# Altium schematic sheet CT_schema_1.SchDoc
size 501 x 485 mm
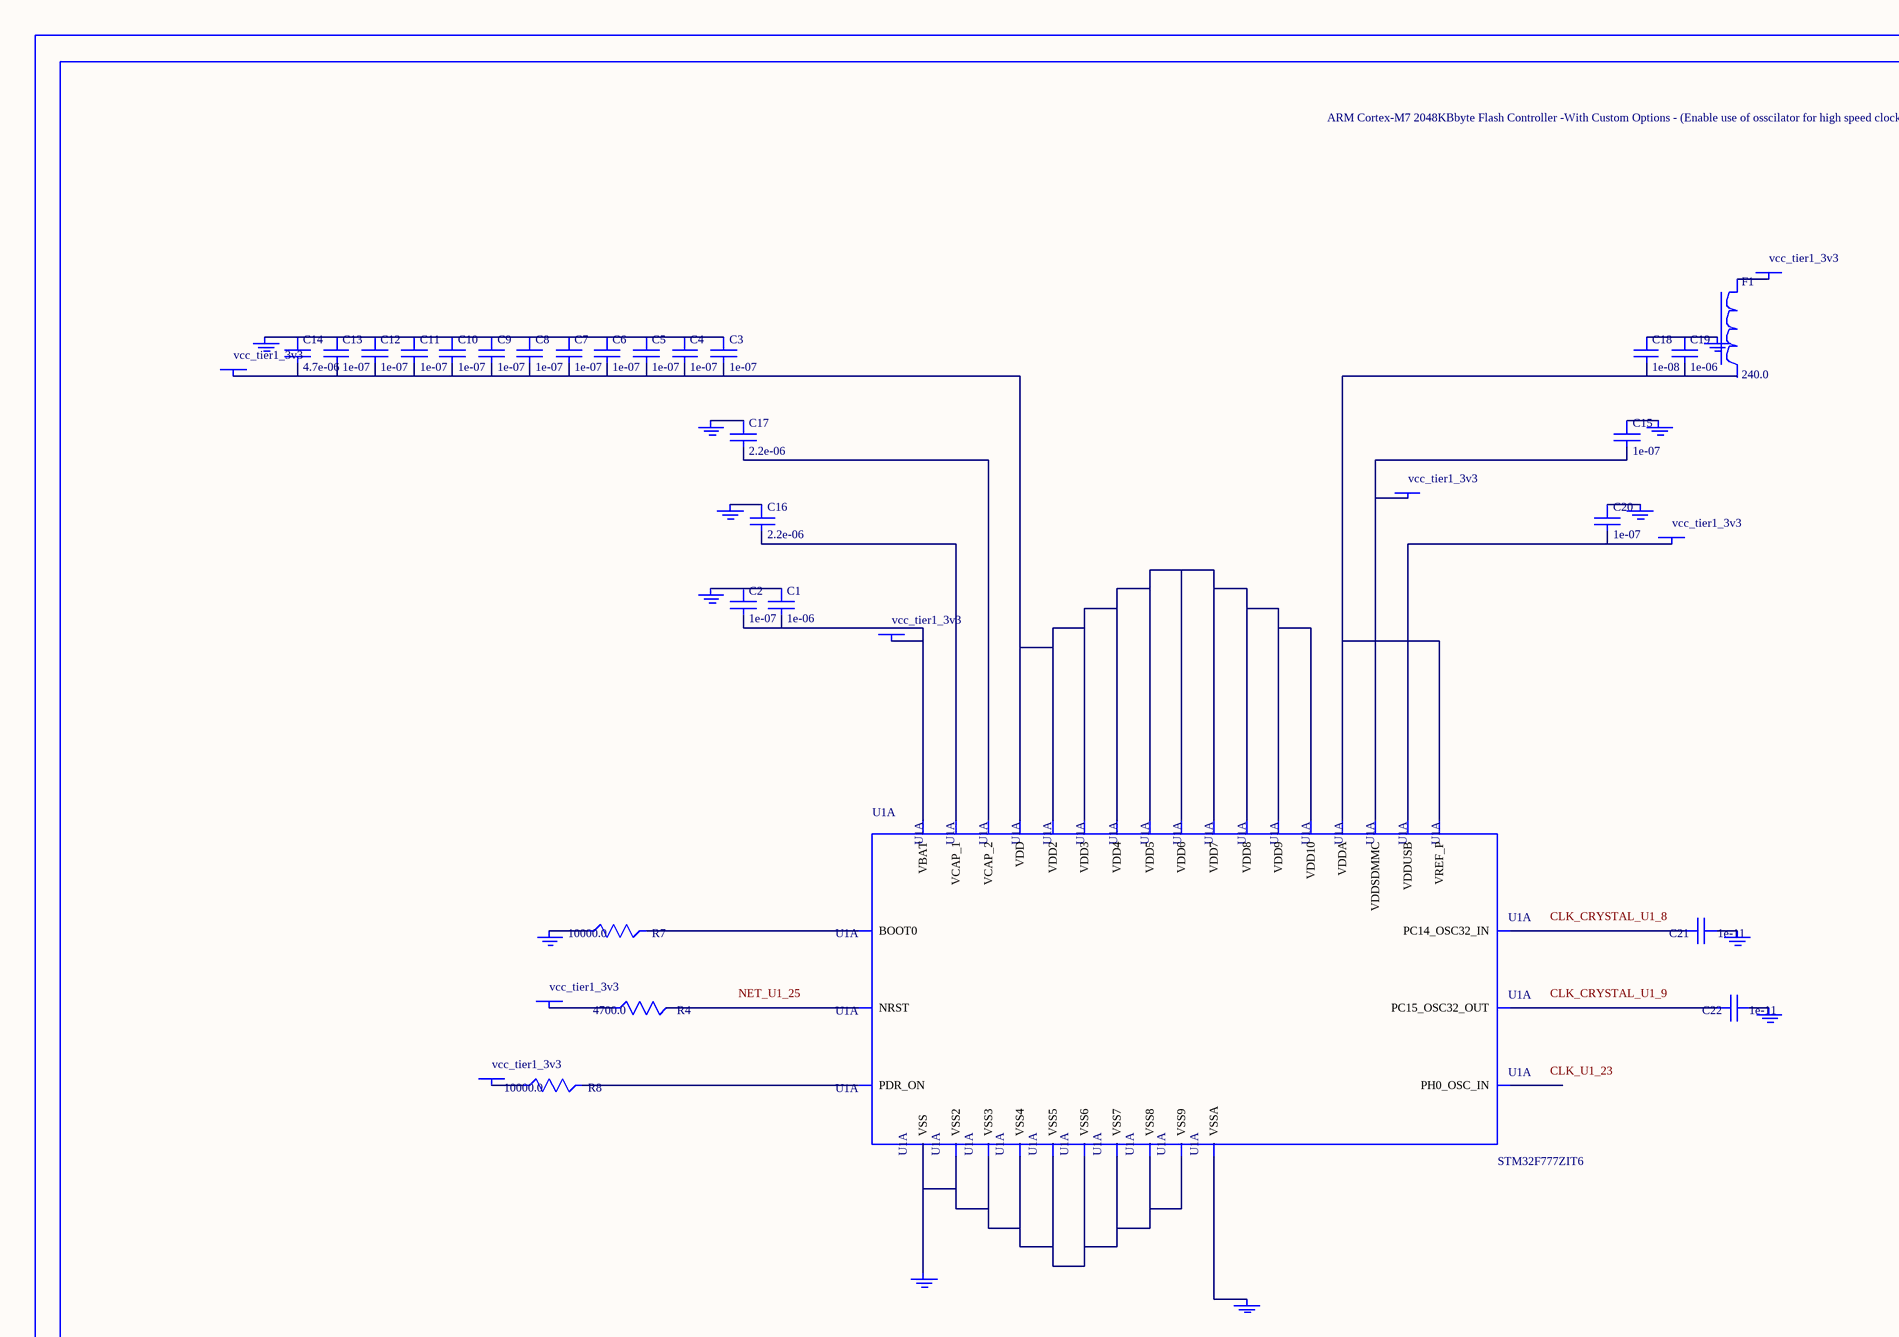
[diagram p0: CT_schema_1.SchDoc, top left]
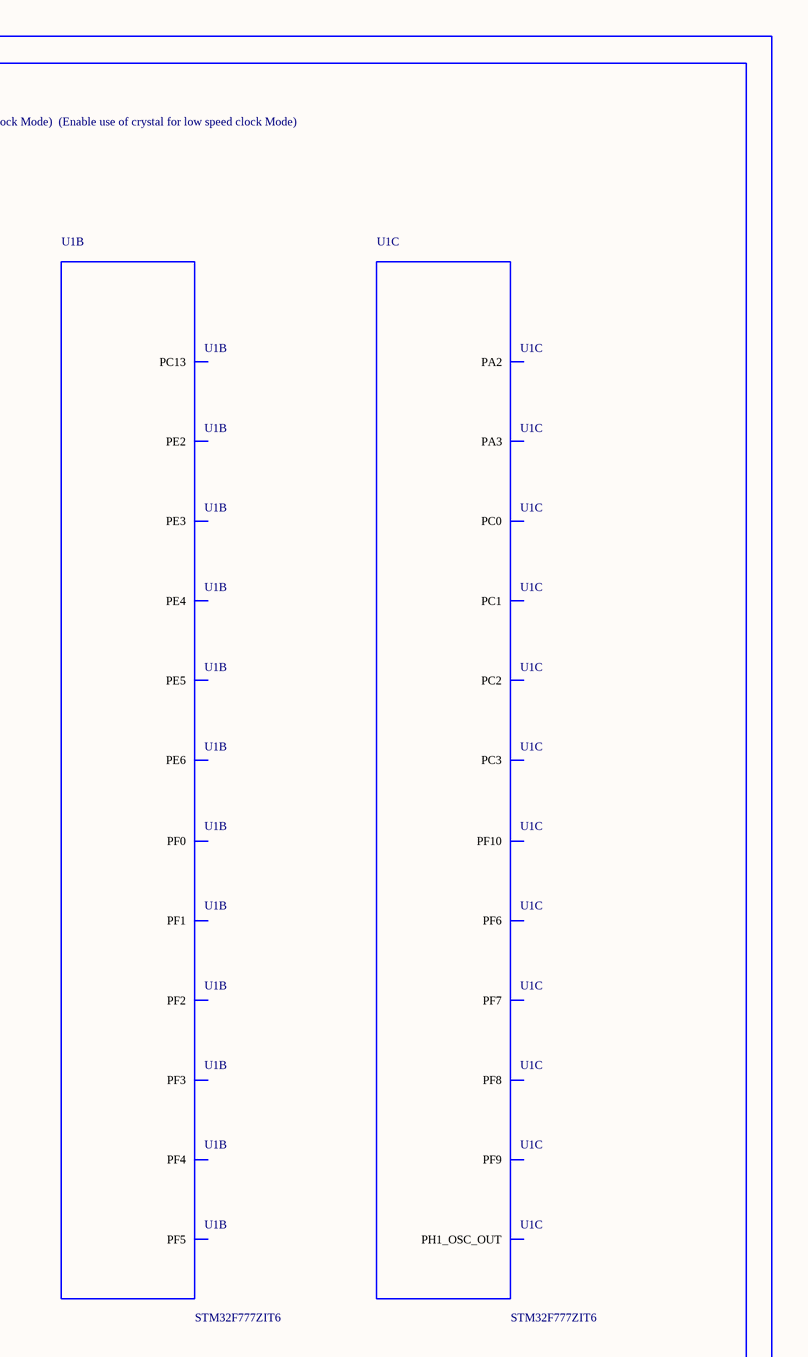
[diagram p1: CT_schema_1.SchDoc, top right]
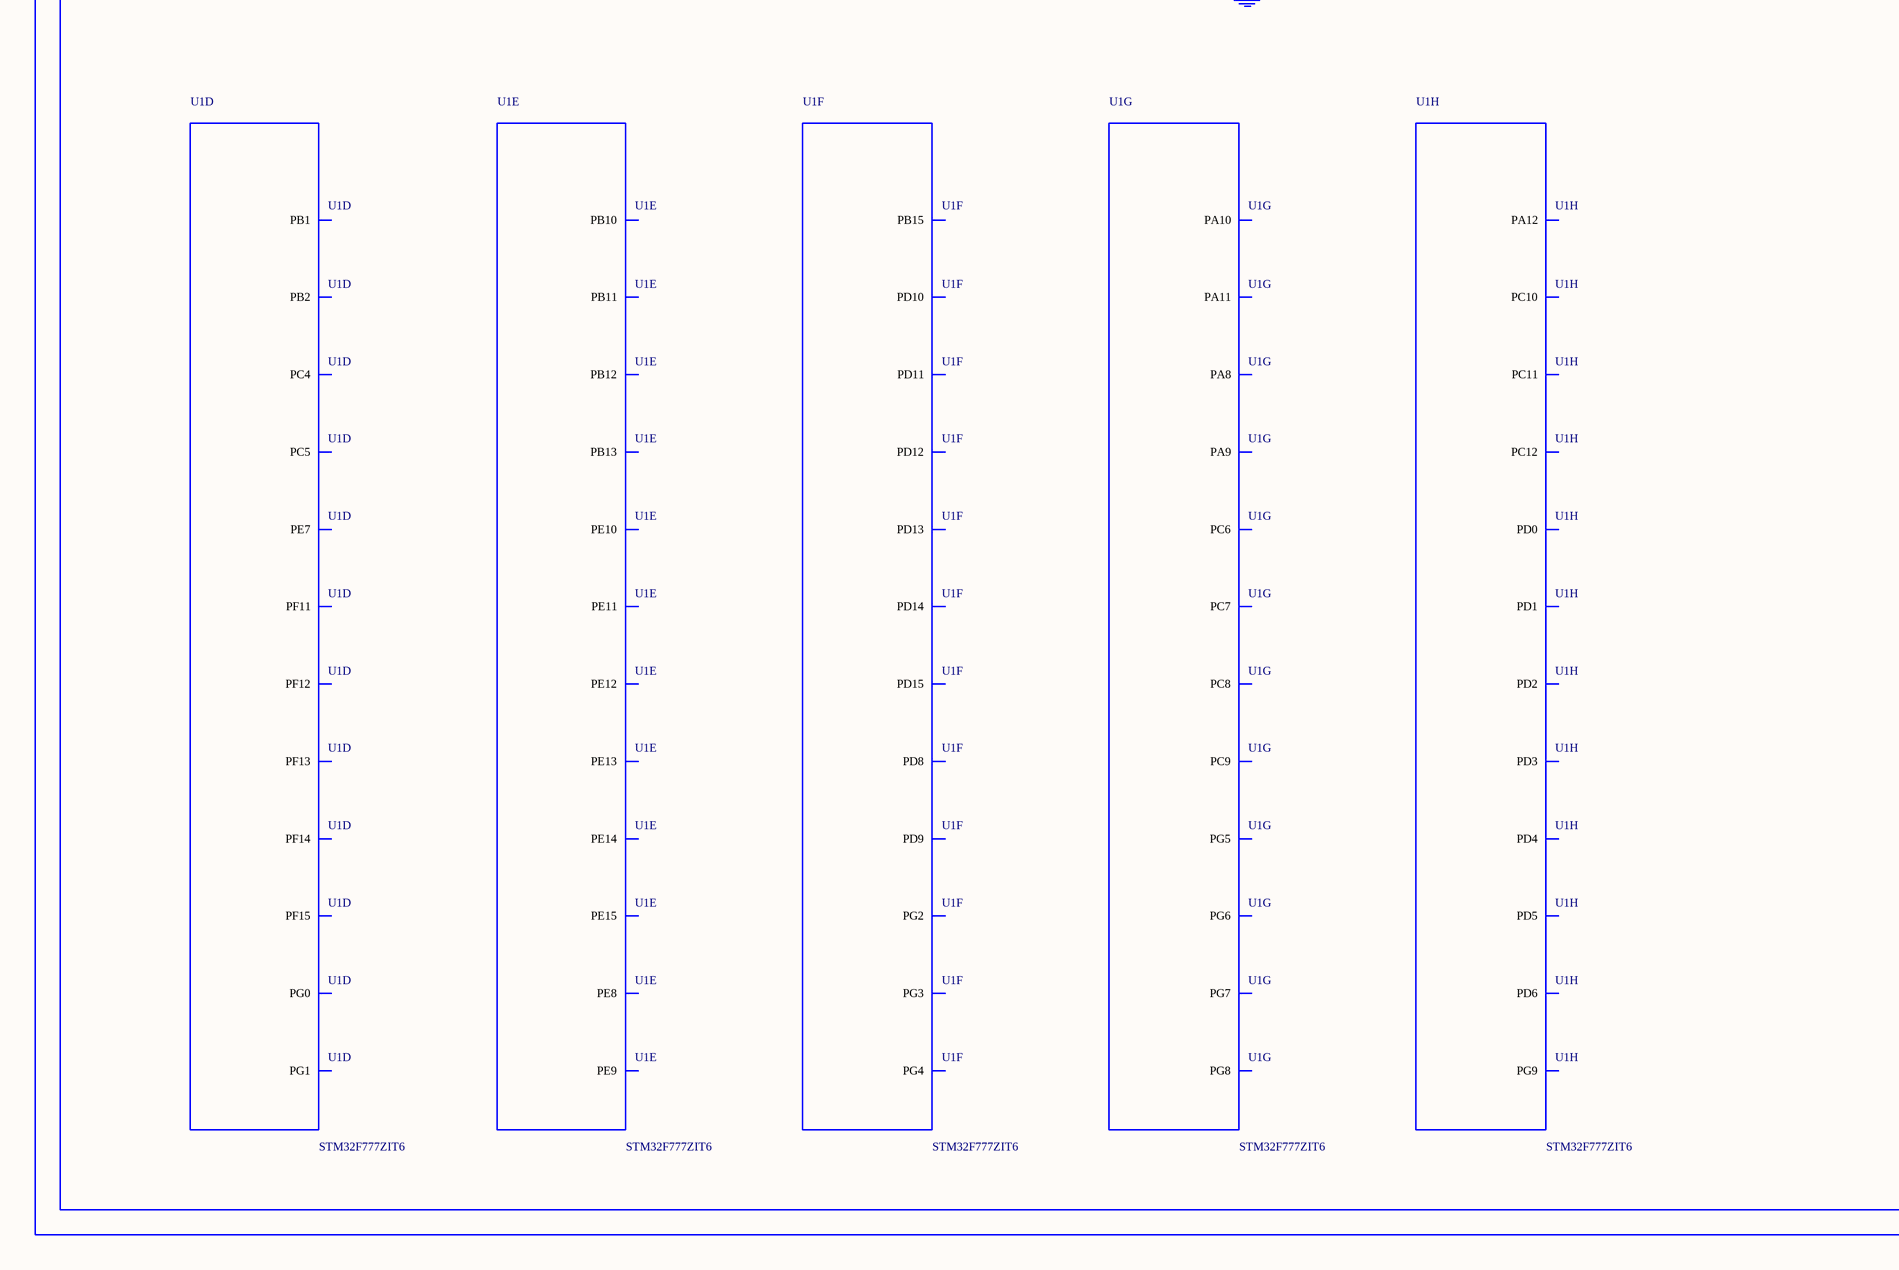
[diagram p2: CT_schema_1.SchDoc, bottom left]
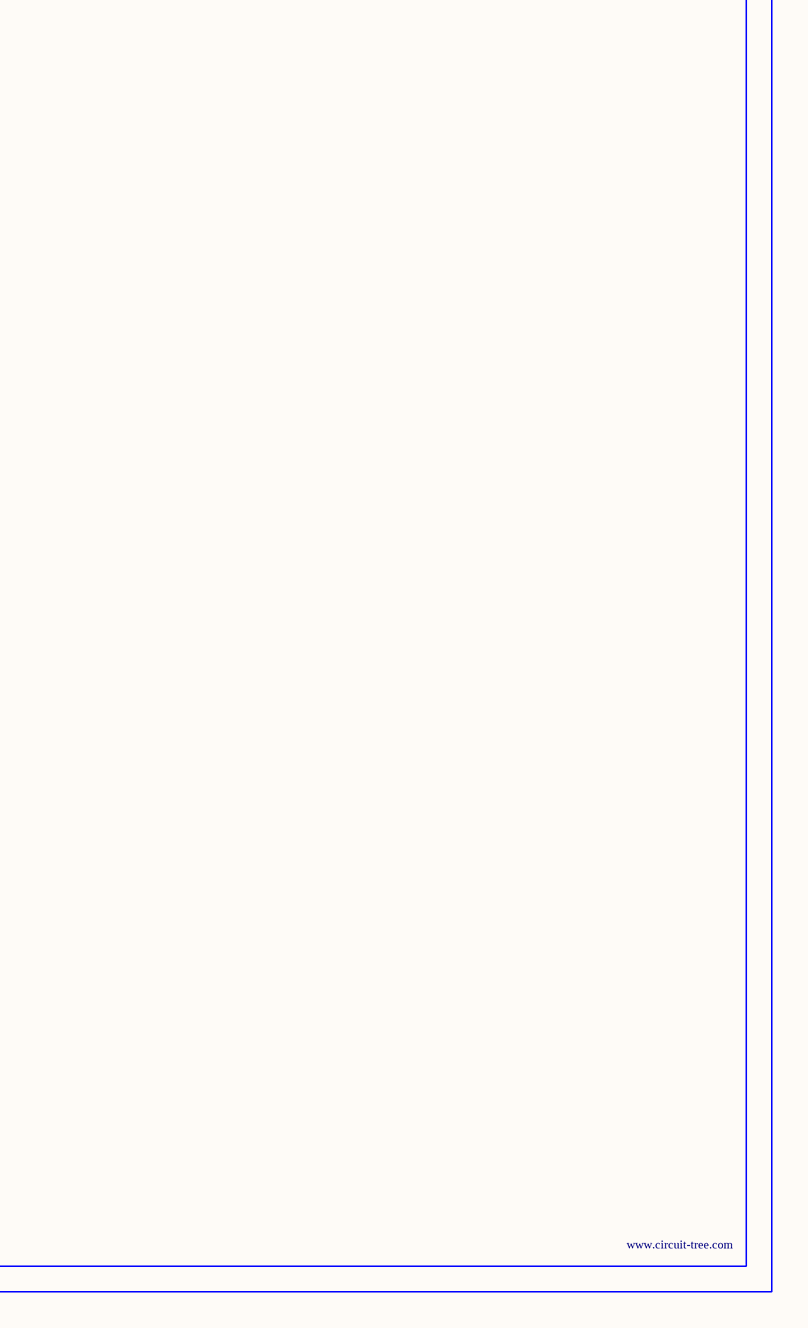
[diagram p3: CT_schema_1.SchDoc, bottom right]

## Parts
BORDER0  (no value)
C1  1e-06  [C0603]
C2  1e-07  [C0603]
C3  1e-07  [C0603]
C4  1e-07  [C0603]
C5  1e-07  [C0603]
C6  1e-07  [C0603]
C7  1e-07  [C0603]
C8  1e-07  [C0603]
C9  1e-07  [C0603]
C10  1e-07  [C0603]
C11  1e-07  [C0603]
C12  1e-07  [C0603]
C13  1e-07  [C0603]
C14  4.7e-06  [C0603]
C15  1e-07  [C0603]
C16  2.2e-06  [C0603]
C17  2.2e-06  [C0603]
C18  1e-08  [C0603]
C19  1e-06  [C0603]
C20  1e-07  [C0603]
C21  1e-11  [C0402]
C22  1e-11  [C0402]
F1  240.0  [L0603]
GND_INSTANCE_0_0  (no value)
GND_INSTANCE_0_1  (no value)
GND_INSTANCE_0_2  (no value)
GND_INSTANCE_0_3  (no value)
GND_INSTANCE_0_4  (no value)
GND_INSTANCE_0_5  (no value)
GND_INSTANCE_0_6  (no value)
GND_INSTANCE_0_7  (no value)
GND_INSTANCE_0_8  (no value)
GND_INSTANCE_0_9  (no value)
GND_INSTANCE_0_10  (no value)
GND_INSTANCE_0_11  (no value)
POWER_INSTANCE_0_0  vcc_tier1_3v3
POWER_INSTANCE_0_1  vcc_tier1_3v3
POWER_INSTANCE_0_2  vcc_tier1_3v3
POWER_INSTANCE_0_3  vcc_tier1_3v3
POWER_INSTANCE_0_4  vcc_tier1_3v3
POWER_INSTANCE_0_5  vcc_tier1_3v3
POWER_INSTANCE_0_6  vcc_tier1_3v3
R4  4700.0  [R0603]
R7  10000.0  [R0603]
R8  10000.0  [R0603]
U1  STM32F777ZIT6  [LQFP144]  (parts A,B,C,D,E,F,G,H of 13)

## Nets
NetC1_1: C1.1 C2.1 GND_INSTANCE_0_0.0(GND)
NetC1_2: C1.2 C2.2 POWER_INSTANCE_0_0.0(PWR) U1.6(VBAT)
NetC3_1: C3.1 C4.1 C5.1 C6.1 C7.1 C8.1 C9.1 C10.1 C11.1 C12.1 C13.1 C14.1 GND_INSTANCE_0_3.0(GND)
NetC3_2: C3.2 C4.2 C5.2 C6.2 C7.2 C8.2 C9.2 C10.2 C11.2 C12.2 C13.2 C14.2 POWER_INSTANCE_0_1.0(PWR) U1.17(VDD) U1.30(VDD2) U1.39(VDD3) U1.52(VDD4) U1.62(VDD5) U1.72(VDD6) U1.84(VDD7) U1.108(VDD8) U1.131(VDD9) U1.144(VDD10)
NetC15_1: C15.1 GND_INSTANCE_0_9.0(GND)
NetC15_2: C15.2 POWER_INSTANCE_0_4.0(PWR) U1.121(VDDSDMMC)
NetC16_1: C16.1 GND_INSTANCE_0_6.0(GND)
NetC16_2: C16.2 U1.71(VCAP_1)
NetC17_1: C17.1 GND_INSTANCE_0_8.0(GND)
NetC17_2: C17.2 U1.106(VCAP_2)
NetC18_1: C18.1 C19.1 GND_INSTANCE_0_5.0(GND)
NetC18_2: C18.2 C19.2 U1.32(VREF_P) U1.33(VDDA)
NetC20_1: C20.1 GND_INSTANCE_0_7.0(GND)
NetC20_2: C20.2 POWER_INSTANCE_0_3.0(PWR) U1.95(VDDUSB)
NetC21_1: C21.1 GND_INSTANCE_0_1.0(GND)
NetC21_2: C21.2 U1.8(PC14_OSC32_IN)
NetC22_1: C22.1 GND_INSTANCE_0_2.0(GND)
NetC22_2: C22.2 U1.9(PC15_OSC32_OUT)
NetF1_1: F1.1 POWER_INSTANCE_0_2.0(PWR)
NetGND_INSTANCE_0_4_0: GND_INSTANCE_0_4.0(GND) U1.31(VSSA)
NetGND_INSTANCE_0_10_0: GND_INSTANCE_0_10.0(GND) R7.1
NetGND_INSTANCE_0_11_0: GND_INSTANCE_0_11.0(GND) U1.16(VSS) U1.38(VSS2) U1.51(VSS3) U1.61(VSS4) U1.83(VSS5) U1.94(VSS6) U1.107(VSS7) U1.120(VSS8) U1.130(VSS9)
NetPOWER_INSTANCE_0_5_0: POWER_INSTANCE_0_5.0(PWR) R8.1
NetPOWER_INSTANCE_0_6_0: POWER_INSTANCE_0_6.0(PWR) R4.1
NetR4_2: R4.2 U1.25(NRST)
NetR7_2: R7.2 U1.138(BOOT0)
NetR8_2: R8.2 U1.143(PDR_ON)

Not connected (* = marked no-connect by the designer): F1 2; U1 1(PE2) 2(PE3) 3(PE4) 4(PE5) 5(PE6) 7(PC13) 10(PF0) 11(PF1) 12(PF2) 13(PF3) 14(PF4) 15(PF5) 18(PF6) 19(PF7) 20(PF8) 21(PF9) 22(PF10) 23(PH0_OSC_IN) 24(PH1_OSC_OUT) 26(PC0) 27(PC1) 28(PC2) 29(PC3) 36(PA2) 37(PA3) 44(PC4) 45(PC5) 47(PB1) 48(PB2) 49(PF11) 50(PF12) 53(PF13) 54(PF14) 55(PF15) 56(PG0) 57(PG1) 58(PE7) 59(PE8) 60(PE9) 63(PE10) 64(PE11) 65(PE12) 66(PE13) 67(PE14) 68(PE15) 69(PB10) 70(PB11) 73(PB12) 74(PB13) 76(PB15) 77(PD8) 78(PD9) 79(PD10) 80(PD11) 81(PD12) 82(PD13) 85(PD14) 86(PD15) 87(PG2) 88(PG3) 89(PG4) 90(PG5) 91(PG6) 92(PG7) 93(PG8) 96(PC6) 97(PC7) 98(PC8) 99(PC9) 100(PA8) 101(PA9) 102(PA10) 103(PA11) 104(PA12) 111(PC10) 112(PC11) 113(PC12) 114(PD0) 115(PD1) 116(PD2) 117(PD3) 118(PD4) 119(PD5) 122(PD6) 124(PG9)

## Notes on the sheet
- Labels drawn without touching a wire or pin: CLK_CRYSTAL_U1_8, CLK_CRYSTAL_U1_9, CLK_U1_23, NET_U1_25

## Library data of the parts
BORDER0 = BORDER_PAGE0
C1 C19 = C0603C105K3RACTU
C2-C13 C15 C20 = 06035C104K4Z2A
C14 = GRM188R6YA475KE15D
C16 C17 = C0603C225K8RACTU
C18 = 06035C103K4Z2A
C21 C22 = C0402C100K3GACTU
F1 = Z0603C241ASMST
GND_INSTANCE_0_0-GND_INSTANCE_0_11 = GND
POWER_INSTANCE_0_0-POWER_INSTANCE_0_6 = PWR
R4 = RC0603JR-074K7L
R7 R8 = RC0603JR-0710KL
